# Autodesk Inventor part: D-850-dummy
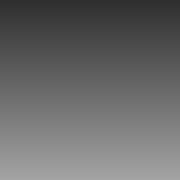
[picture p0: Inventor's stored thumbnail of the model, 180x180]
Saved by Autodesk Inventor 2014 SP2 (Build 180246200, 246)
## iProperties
Created: 2020-01
Part Number: D-850-dummy
Material: Generic
Catalog Web Link: www.cadenas.de
Description: Piston Rod Clevis for Original Line Cylinders - dummy-
Vendor: BIMBA
Document SubType Name: Modeling
Designer: psadmin
Manufacturer: BIMBA
Density: 1 g/cm^3
Appearance: PSOLRGB-208-108-81
Category: PARTsolutions
Company: BIMBA
Title: D-850-dummy
Author: Cadenas PARTsolutions
PSOL_IDENT_0: {$CADENAS_DATA\23d-libs\bimba\bimba_brand\bimba_imperial\bimba_full_line\original_line_cylinders\acc
PSOL_IDENT_1: essories\piston_rod_clevis_dummy.prj},209 {VTYP=3D},{NB=D-850-dummy},{LINA=D-850-dummy},{NN=Piston R
PSOL_IDENT_2: od Clevis for Original Line Cylinders - dummy},{DATE=23.12.2019 10:36:52},{GEOMDATE=10.12.2012 09:59
PSOL_IDENT_3: :00},{VERSION=},{LINEID=20},{WBVAR=},{WBNUMERIC=}  {NB=D-850-dummy},{LINA=D-850-dummy},{KT=DUMMY},{P
PSOL_IDENT_4: N=D-850},{MAT=Zinc-Plated Carbon Steel},{DWGRR=D-5406},{DWGCP=D-12304},{DWGREC=D-14043},{DWGN=D-5288
PSOL_IDENT_5: },{MNMAT=},{TH=0.07000000},{TO=0.76000000},{TO1=0.20000000},{L1=0.75000000},{B=0.1200},{L2=0.3750},{
PSOL_IDENT_6: L=0.93700}
NN: Piston Rod Clevis for Original Line Cylinders - dummy
NB: D-850-dummy
NBSYN: $PN.-dummy
LINA: D-850-dummy
PN: D-850
MAT: Zinc-Plated Carbon Steel
DWGRR: D-5406
DWGCP: D-12304
DWGREC: D-14043
DWGN: D-5288
TH: 0.07
TO: 0.76
TO1: 0.2
L1: 0.75
B: 0.12
L2: 0.375
L: 0.937
SUPPLIER: BIMBA
ARTICLENO: D-850-dummy
BOMINFO: D-850-dummy
CREATOR: CADENAS GmbH
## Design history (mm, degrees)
node "dummy_XY"
node "dummy_YZ"
node "dummy_ZX"
node "dummy_X"
node "dummy_Y"
node "dummy_Z"
node "dummy_Center"
node "from_prc_XY"
node "from_prc_YZ"
node "from_prc_ZX"
node "from_prc_X"
node "from_prc_Y"
node "from_prc_Z"
node "from_prc_Center"
node "piston_rod_clevis_dummy_XY"
node "piston_rod_clevis_dummy_YZ"
node "piston_rod_clevis_dummy_ZX"
node "piston_rod_clevis_dummy_X"
node "piston_rod_clevis_dummy_Y"
node "piston_rod_clevis_dummy_Z"
node "piston_rod_clevis_dummy_Center"
node "to_cyl_XY"
node "to_cyl_YZ"
node "to_cyl_ZX"
node "to_cyl_X"
node "to_cyl_Y"
node "to_cyl_Z"
node "to_cyl_Center"
